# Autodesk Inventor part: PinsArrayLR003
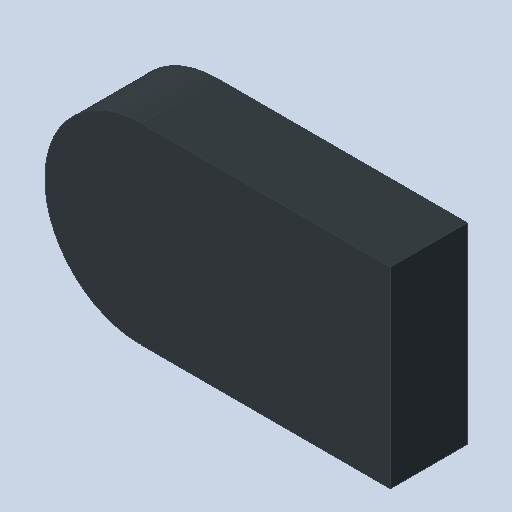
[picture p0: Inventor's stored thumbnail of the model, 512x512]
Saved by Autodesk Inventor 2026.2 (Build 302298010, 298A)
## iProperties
Created: 2026-10
Part Number: PinsArrayLR003
Material: Générique
Document SubType Name: Modeling
Designer: mel
Density: 1 g/cm^3
Appearance: Par défaut
Author: mel
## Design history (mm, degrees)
feature "Base1"
node "Solide1"
